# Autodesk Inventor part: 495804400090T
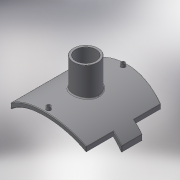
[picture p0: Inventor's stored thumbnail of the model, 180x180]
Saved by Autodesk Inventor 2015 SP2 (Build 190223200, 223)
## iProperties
Created: 2017-10
Part Number: 495804400090T
Material: Generic
Description: PLASSON BRANCH SADDLE 250-400X90
Document SubType Name: Modeling
Designer: KIM
Density: 1 g/cm^3
Appearance: Default
Author: KIM
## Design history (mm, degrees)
derived "495804 (SECOND).ipt"
feature "Solid1::495804 (SECOND).ipt"
tag "TaggingFeature1"
body "Solid1"
other parameters: "d1" = 15, "d2" = 274.5, "d4" = 0, "d5" = 305, "d6" = 75, "d7" = 0, "d8" = 135, "d10" = 0, "d11" = 2, "d12" = 225.6, "d13" = 14, "d14" = 135, "d16" = 5 deg, "d18" = 4, "d19" = 14, "d20" = 0, "d21" = 3, "d22" = 0, "d23" = 317, "d25" = 16, "d26" = 72, "d28" = 0, "d29" = 9.6, "d31" = 0, "d32" = 30.6, "d33" = 0, "d34" = 4, "d35" = 0.8, "B_" = 305, "H_" = 102, "x_" = 15, "D_" = 16
